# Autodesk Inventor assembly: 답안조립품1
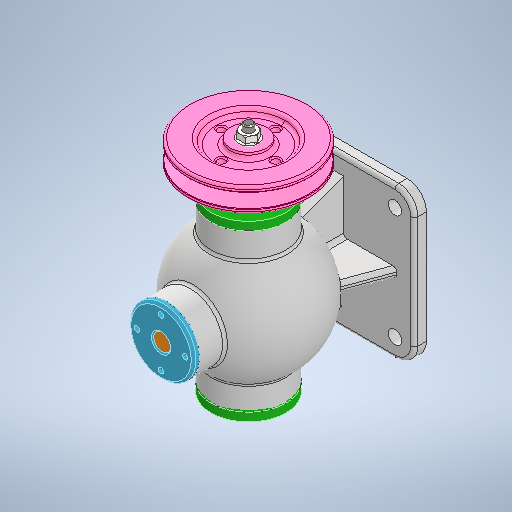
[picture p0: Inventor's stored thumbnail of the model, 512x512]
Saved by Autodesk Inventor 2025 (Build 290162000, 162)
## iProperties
Created: 2025-08
Part Number: 답안조립품1
Document SubType Name: Assembly
Designer: infra017
Author: infra017
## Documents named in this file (13)
- C:\Users\infra017\Desktop\750807V1007\답안조립품1.iam
- C:\Users\infra017\Desktop\750807V1007\본체.ipt
- C:\Users\infra017\Desktop\새 폴더\상부커버\상부커버.ipt
- C:\Users\infra017\Desktop\새 폴더\슬라이드\슬라이드.ipt
- C:\Users\infra017\Desktop\새 폴더\앞커버\앞커버.ipt
- C:\Users\infra017\Desktop\새 폴더\키 4 x 4 x 12\키 4 x 4 x 12.ipt
- C:\Users\infra017\Desktop\새 폴더\편심축\편심축.ipt
- C:\Users\infra017\Desktop\750807V1007\베어링- 6202\베어링- 6202.ipt
- C:\Users\infra017\Desktop\750807V1007\앞커버\앞커버.ipt
- C:\Users\infra017\Desktop\750807V1007\볼트 M4 x 16\볼트 M4 x 16.ipt
- C:\Users\infra017\Desktop\750807V1007\볼트 M4 x 12\볼트 M4 x 12.ipt
- C:\Users\infra017\Desktop\750807V1007\V-벨트풀리\V-벨트풀리.ipt
- C:\Users\infra017\Desktop\750807V1007\너트 M8\너트 M8.ipt
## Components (1 placed, 1 different names)
1. V-벨트풀리:1
